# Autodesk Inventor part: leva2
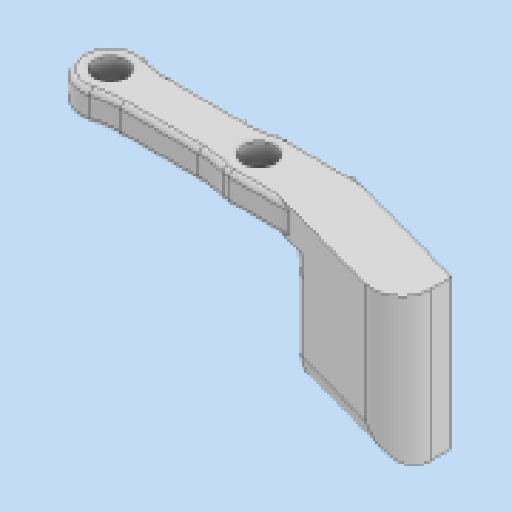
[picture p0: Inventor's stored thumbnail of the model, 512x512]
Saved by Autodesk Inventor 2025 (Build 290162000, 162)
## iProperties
Created: 2026-03
Part Number: leva2
Material: Generico
Document SubType Name: Modeling
Designer: R5800u
Density: 1 g/cm^3
Appearance: Default
Author: R5800u
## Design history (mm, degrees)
sketch "Schizzo1"
  geometry: L1 (7.5, 2.5)-(-7.5, 2.5); L2 (-7.5, 2.5)-(-7.5, -2.5); L3 (-7.5, -2.5)-(7.5, -2.5); L4 (7.5, -2.5)-(7.5, 2.5); L5 (7.5, 2.5)-(-7.5, -2.5); L6 (-7.5, 2.5)-(7.5, -2.5); C1 r 3 at (7.5, 0); C2 r 3 at (-7.5, 0); 5 further points
  constraints: 12 end point, 4 midpoint, 2 centre point, 2 parallel, 1 horizontal, 1 perpendicular
  dimensions: "d0" = 15 distance of L3.end L2.end; "d1" = 5 distance of L2.end L1.end; "d4" = 6 diameter of C1; "d5" = 6 diameter of C2
extrude "Estrusione1" new body sketch "Schizzo1" distance "d2" = 3; taper "d3" = 0 deg
sketch "Schizzo2"
  geometry: A1 r 3 centre (7.5, 0) between (5.842, -2.5) and (5.842, 2.5) reference; A2 r 3 centre (-7.5, 0) between (-5.842, 2.5) and (-5.842, -2.5) reference; 3 further points
  constraints: 2 coincident
hole "Foro1" sketch "Schizzo2" at (7.5, 0), (-7.5, 0) diameter "d6" = 3.2; stored, may be unused: countersink angle "d10" = 90 deg, drill point angle "d12" = 118 deg; dims "d7" = 6, "d8" = 6.5, "d9" = 3.4, "d11" = 8
sketch "Schizzo3"
  geometry: L1 (5.842, 2.5)-(-5.842, 2.5) reference; L2 (-5.842, -2.5)-(5.842, -2.5) reference; L3 (7.5, 0)-(7.5, 3); L4 (7.5, 0)-(7.5, -3); L5 (7.5, 3)-(13.5, 3); L6 (13.5, 3)-(13.5, -3); L7 (13.5, -3)-(7.5, -3); L8 (7.5, -3)-(7.5, 3); L9 (13.5, -3)-(10.036, 3); C1 r 1.6 at (-7.5, 0) reference; C2 r 1.6 at (7.5, 0) reference; A1 r 3 centre (7.5, 0) between (5.842, -2.5) and (5.842, 2.5) reference; A2 r 3 centre (-7.5, 0) between (-5.842, 2.5) and (-5.842, -2.5) reference; 2 further points
  constraints: 14 end point, 3 point on line, 2 parallel, 2 point on circle, 1 horizontal, 1 perpendicular, 1 vertical
  dimensions: "d13" = 6 distance of L6.end L7.end; "d16" = 30 deg angle of L9 L6
extrude "Estrusione2" join sketch "Schizzo3" stored distance "d14" = 10; taper "d15" = 0 deg
fillet "Raccordo1" dims "d17" = 10
sketch "Schizzo5"
  geometry: L1 (13.5, -3)-(13.5, 3) reference; L2 (13.5, -3)-(16.5, 2.196); L3 (16.5, 2.196)-(13.5, 3); L4 (13.5, 3)-(16.098, 1.5); 1 further point
  constraints: 6 end point, 1 perpendicular, 1 point on line
  dimensions: "d22" = 6 distance of L1.start L2.end; "d23" = 30 deg angle of L1 L2
extrude "Estrusione4" join sketch "Schizzo5" stored distance "d24" = 10; taper "d25" = 0 deg
sketch "Schizzo6"
  geometry: L1 (13.5, -3)-(13.5, 3) reference; L2 (13.5, 3)-(27.964, -0.973); L3 (27.964, -0.973)-(27.964, -6.973); L4 (27.964, -6.973)-(13.5, -3); L5 (27.964, -3.973)-(13.5, 0); 1 further point
  constraints: 8 end point, 2 midpoint, 1 parallel
  dimensions: "d26" = 6 distance of L2.end L3.end; "d27" = 74.64 deg angle of L1 L2; "d33" = 15 distance of L5.start L5.end
extrude "Estrusione5" join sketch "Schizzo6" distance "d28" = 15; taper "d29" = 0 deg
chamfer "Smusso1" distance "d30" = 2; stored, may be unused: second distance "d31" = 2, angle "d32" = 45 deg
fillet "Raccordo2" dims "d34" = 2
fillet "Raccordo3" dims "d35" = 3
fillet "Raccordo4" dims "d36" = 0.53
fillet "Raccordo5" dims "d37" = 0.5
node "Solido1"
node "Linea chiusa proiettata1"
